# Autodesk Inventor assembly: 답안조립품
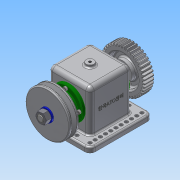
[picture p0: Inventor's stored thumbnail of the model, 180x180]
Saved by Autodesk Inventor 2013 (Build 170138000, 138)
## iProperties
Created: 2018-11
Part Number: 답안조립품
Document SubType Name: Assembly
Designer: Administrator
Author: Administrator
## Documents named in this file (13)
- C:\Users\Administrator\Desktop\481107V1014\답안조립품.iam
- C:\Users\Administrator\Desktop\481107V1014\본체.ipt
- C:\Users\Administrator\Desktop\481107V1014\V벨트풀리.ipt
- C:\Users\Administrator\Desktop\481107V1014\너트 M12x1.25.ipt
- C:\Users\Administrator\Desktop\481107V1014\베어링 6203.ipt
- C:\Users\Administrator\Desktop\481107V1014\볼트 M4.ipt
- C:\Users\Administrator\Desktop\481107V1014\부시.ipt
- C:\Users\Administrator\Desktop\481107V1014\스퍼기어.ipt
- C:\Users\Administrator\Desktop\481107V1014\오일 실 26 38 8.ipt
- C:\Users\Administrator\Desktop\481107V1014\와셔 12x24.ipt
- C:\Users\Administrator\Desktop\481107V1014\축.ipt
- C:\Users\Administrator\Desktop\481107V1014\커버.ipt
- C:\Users\Administrator\Desktop\481107V1014\키 5x5x12.ipt
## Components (1 placed, 1 different names)
1. V벨트풀리:1
